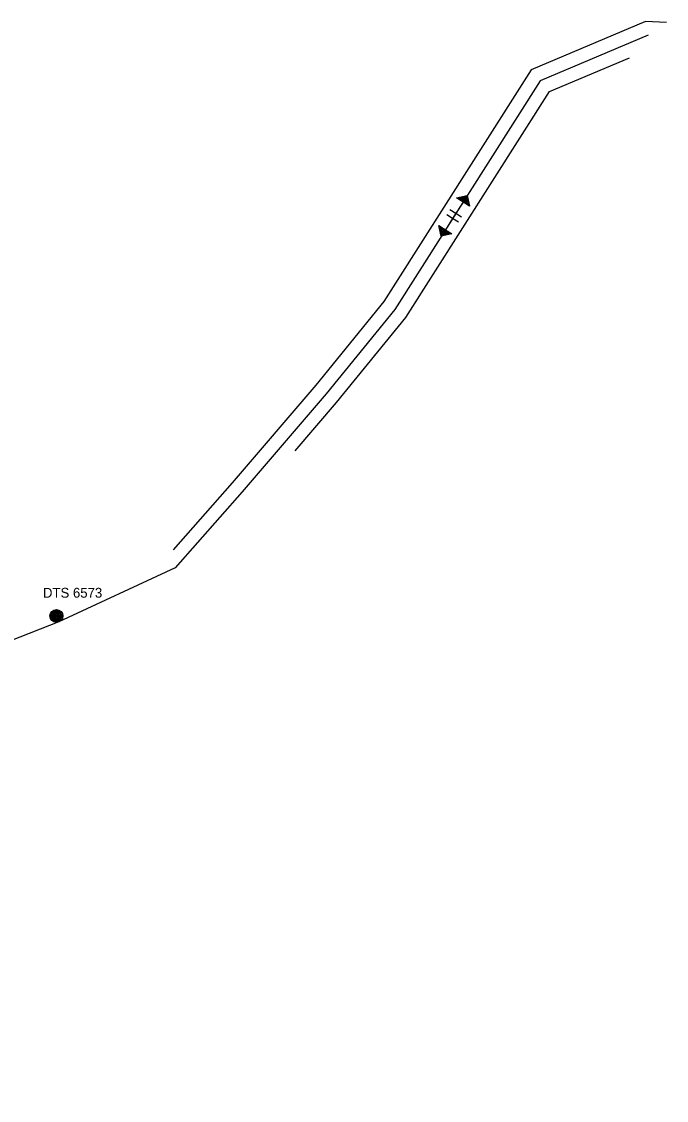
# Model space of a CAD drawing. Extents: x -444841 to -429545, y -1135312 to -1129851.
# Drawn here: x -443164 to -442641, y -1133866 to -1132989 of the extents above; entities that cross this region are included whole.
import ezdxf

# ---------------------------------------------------------------- set-up
doc = ezdxf.new("R2010")
doc.units = 0
for name, color, linetype in [('Vrstva 10', 7, 'Continuous'), ('Vrstva 11', 7, 'Continuous'), ('Vrstva 13', 7, 'Continuous'), ('Vrstva 15', 7, 'Continuous')]:
    doc.layers.add(name, color=color, linetype=linetype)

msp = doc.modelspace()

# ---------------------------------------------------------------- linework, layer by layer
at = {"layer": 'Vrstva 10'}
for p, q in [((-442814.23, -1133149.26), (-442818.96, -1133146.26)), ((-442811.68, -1133145.25), (-442816.4, -1133142.24)), ((-442806.95, -1133148.25), (-442811.68, -1133145.25)), ((-442809.51, -1133152.27), (-442814.23, -1133149.26))]:
    msp.add_line(p, q, dxfattribs=at)
for points in [[(-442655.45, -1133000.4), (-442743.08, -1133037.44), (-442861.29, -1133223.22), (-442916.94, -1133291.71), (-442985.18, -1133371.52), (-443039.73, -1133433.23), (-443134.16, -1133477.18), (-443220.61, -1133510.88), (-443495.13, -1133621.94), (-443578.91, -1133658), (-443660.35, -1133693.44), (-443732.64, -1133749.17), (-443815.26, -1133811.98), (-443852.04, -1133842.24), (-443880.94, -1133866.11)], [(-442805.81, -1133136.03), (-442812.95, -1133147.25), (-442820.09, -1133158.48)], [(-443134.52, -1133477.08), (-443134.74, -1133476.42), (-443134.93, -1133475.87)]]:
    msp.add_lwpolyline(points, dxfattribs=at)
for points in [[(-442800.5, -1133139.42), (-442811.13, -1133132.65), (-442802.43, -1133130.72)], [(-442801.55, -1133137.92), (-442809.33, -1133132.97), (-442802.96, -1133131.55)], [(-442802.6, -1133136.42), (-442807.52, -1133133.28), (-442803.49, -1133132.39)], [(-442803.65, -1133134.92), (-442805.72, -1133133.6), (-442804.03, -1133133.22)], [(-442814.78, -1133161.86), (-442823.48, -1133163.79), (-442825.41, -1133155.09)], [(-442816.58, -1133161.54), (-442822.94, -1133162.96), (-442824.36, -1133156.59)], [(-442818.38, -1133161.22), (-442822.41, -1133162.12), (-442823.31, -1133158.09)], [(-442820.18, -1133160.91), (-442821.88, -1133161.28), (-442822.26, -1133159.59)]]:
    msp.add_lwpolyline(points, close=True, dxfattribs=at)
at = {"layer": 'Vrstva 11'}
for radius in [5.25, 4.55, 3.85, 3.15, 2.45, 1.75, 1.05, 0.35]:
    msp.add_circle((-443136.14, -1133472.38), radius, dxfattribs=at)
at = {"layer": 'Vrstva 15'}
for points in [[(-442640.55, -1132990.12), (-442657.42, -1132989.29), (-442750.52, -1133028.64), (-442870.23, -1133216.78), (-442925.39, -1133284.67), (-442993.48, -1133364.3), (-443041.44, -1133418.56)], [(-442942.17, -1133338.15), (-442908.49, -1133298.76), (-442852.35, -1133229.66), (-442735.64, -1133046.24), (-442670.57, -1133018.73)]]:
    msp.add_lwpolyline(points, dxfattribs=at)

# ---------------------------------------------------------------- texts
at = {"layer": 'Vrstva 13'}
msp.add_text('DTS 6573', height=8, dxfattribs=at).set_placement((-443147.11, -1133457.52))

doc.saveas('drawing.dxf')
